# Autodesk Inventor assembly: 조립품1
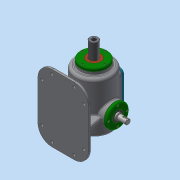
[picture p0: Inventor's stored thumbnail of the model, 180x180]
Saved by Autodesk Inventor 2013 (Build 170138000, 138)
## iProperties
Created: 2019-10
Part Number: 조립품1
Document SubType Name: Assembly
Designer: dgall
Author: dgall
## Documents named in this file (17)
- C:\Users\dgall\Desktop\391004v1015\조립품1.iam
- C:\Users\dgall\Desktop\391004v1015\01본체.ipt
- C:\Users\dgall\Desktop\391004v1015\02개스킷 A.ipt
- C:\Users\dgall\Desktop\391004v1015\03개스킷 B.ipt
- C:\Users\dgall\Desktop\391004v1015\04베어링 6205.ipt
- 베어링 6205.ipt
- C:\Users\dgall\Desktop\391004v1015\05축 커버.ipt
- C:\Users\dgall\Desktop\391004v1015\06오일 실 25 38 8.ipt
- C:\Users\dgall\Desktop\391004v1015\07슬라이드 커버.ipt
- C:\Users\dgall\Desktop\391004v1015\08부시.ipt
- C:\Users\dgall\Desktop\391004v1015\09슬라이드.ipt
- C:\Users\dgall\Desktop\391004v1015\10편심축.ipt
- C:\Users\dgall\Desktop\391004v1015\11볼트 M4x0.7.ipt
- C:\Users\dgall\Desktop\391004v1015\12상부커버.ipt
- C:\Users\dgall\Desktop\391004v1015\13고정플레이트.ipt
- C:\Users\dgall\Desktop\391004v1015\14육각머리볼트 M4.ipt
- C:\Users\dgall\Desktop\391004v1015\15가변스프링.ipt
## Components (29 placed, 14 different names)
1. 01본체:1
2. 02개스킷 A:1
3. 03개스킷 B:1
4. 05축 커버:1 — 각도:1
5. 06오일 실 25 38 8:1
6. 07슬라이드 커버:1
7. 08부시:1
8. 09슬라이드:1
9. 10편심축:1 — 각도:1
10. 12상부커버:1
11. 13고정플레이트:1
12. 14육각머리볼트 M4:1
13. 15가변스프링:1
14. 03개스킷 B:2
15. 05축 커버:2
16. 06오일 실 25 38 8:2
17. 14육각머리볼트 M4:2
18. M4x0.7:3
19. M4x0.7:1
20. M4x0.7:4
21. M4x0.7:5
22. M4x0.7:6
23. M4x0.7:7
24. M4x0.7:8
25. M4x0.7:9
26. M4x0.7:2
27. M4x0.7:10
28. M4x0.7:11
29. M4x0.7:12
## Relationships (1: Angle 1)
- 각도:1 [Angle]: 05축 커버:1 ↔ 10편심축:1
